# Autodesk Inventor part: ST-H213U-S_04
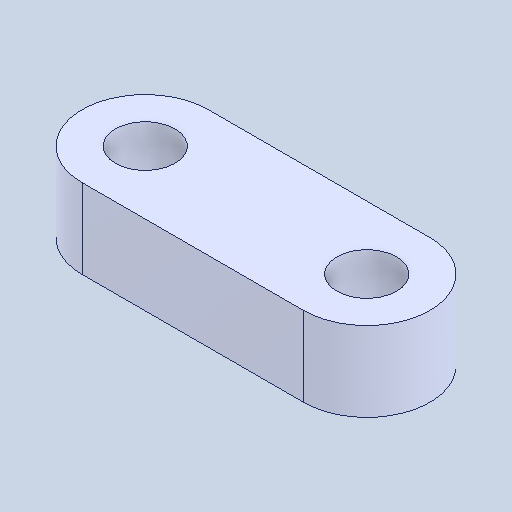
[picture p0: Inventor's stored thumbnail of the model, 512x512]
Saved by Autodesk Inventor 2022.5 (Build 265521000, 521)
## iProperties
Created: 2024-07
Part Number: ST-H213U-S_04
Material: 一般
Document SubType Name: Modeling
Designer: ImaoCorp
Density: 1 g/cm^3
Appearance: 既定
Author: ImaoCorp
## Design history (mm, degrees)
feature "ST-H213U-S_04"
node "ソリッド1"
